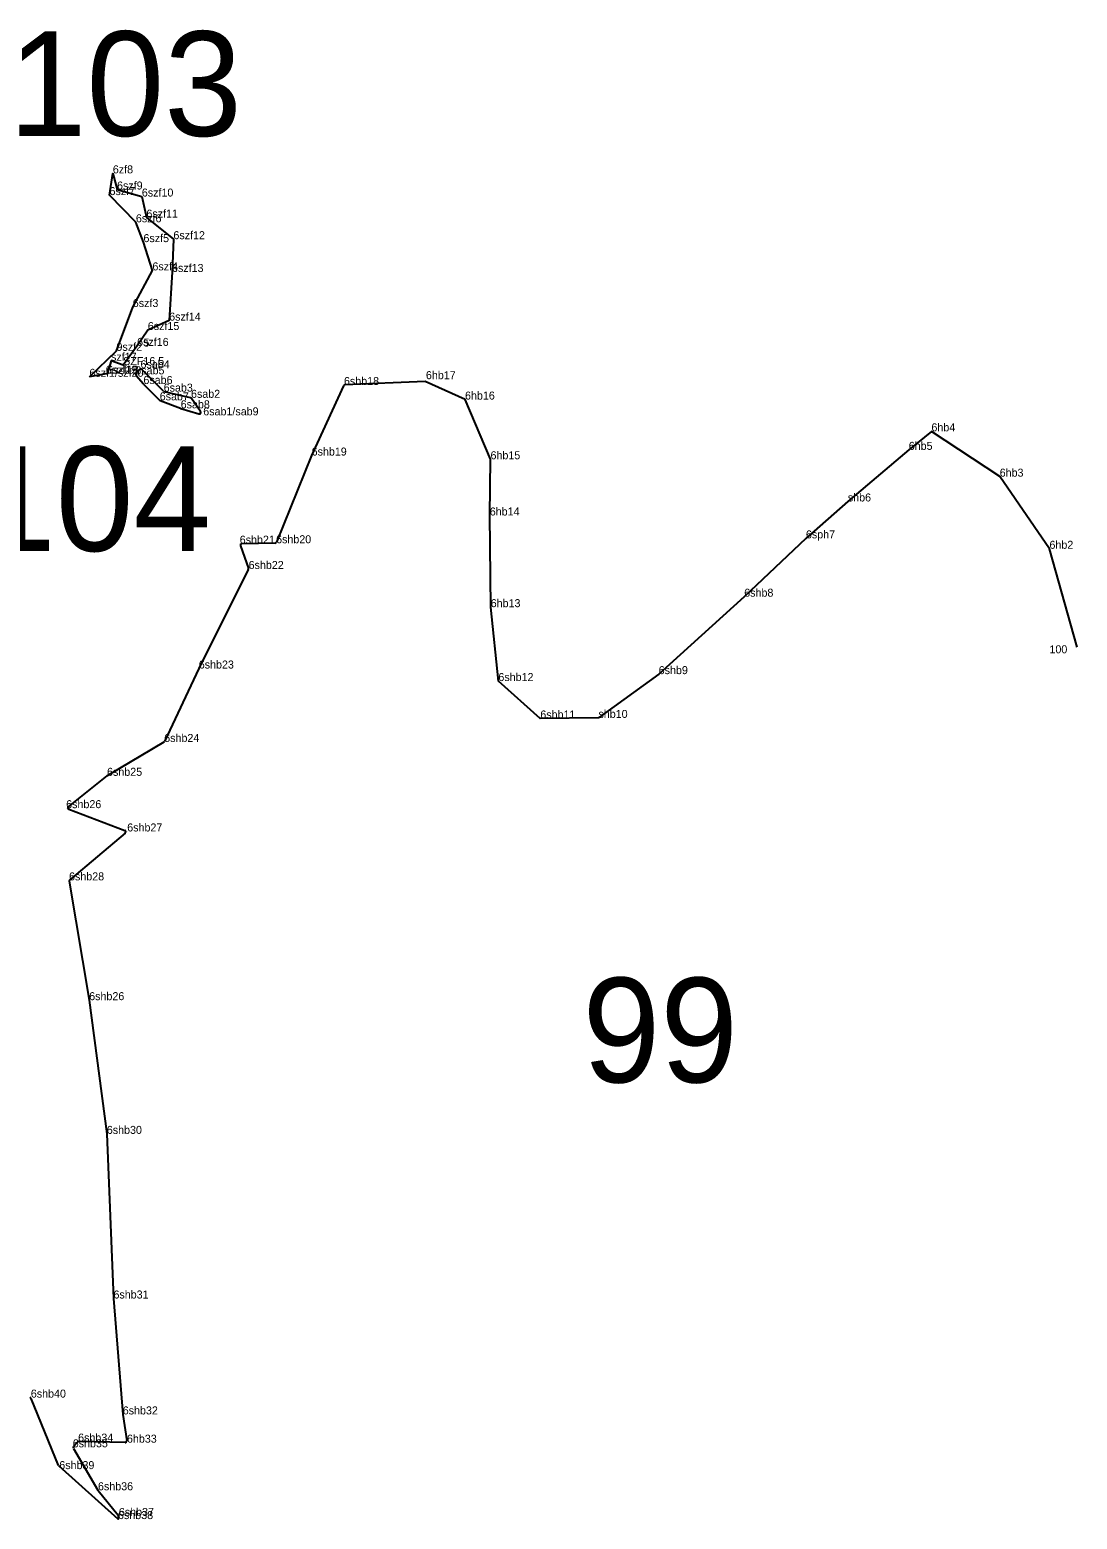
# Model space of a CAD drawing. Extents: x 2072529 to 2268796, y 436423 to 470397.
# Drawn here: x 2138755 to 2139410, y 443063 to 443993 of the extents above; entities that cross this region are included whole.
import ezdxf

# ---------------------------------------------------------------- set-up
doc = ezdxf.new("R2010")
doc.units = 0
for name, color, linetype in [('Default', 7, 'Continuous'), ('Exist Environmental Wetland Boundary Cogo Point CELL', 7, 'Continuous'), ('Exist Hydro Jurisdictional Stream or Body of Water NEU Mitigable', 7, 'Continuous'), ('Exist Hydro Jurisdictional Stream or Body of Water NEU Mitigable Cogo Comment', 7, 'Continuous')]:
    doc.layers.add(name, color=color, linetype=linetype)

msp = doc.modelspace()

# ---------------------------------------------------------------- linework, layer by layer
at = {"layer": 'Exist Environmental Wetland Boundary Cogo Point CELL'}
for p, q in [((2138807.29, 443903.7), (2138807.29, 443903.7)), ((2138809.92, 443893.61), (2138809.92, 443893.61)), ((2138805.21, 443890.14), (2138805.21, 443890.14)), ((2138825.43, 443889.22), (2138825.43, 443889.22)), ((2138821.71, 443873.14), (2138821.71, 443873.14)), ((2138828.27, 443876.07), (2138828.27, 443876.07)), ((2138826.43, 443860.76), (2138826.43, 443860.76)), ((2138845.15, 443862.59), (2138845.15, 443862.59)), ((2138832.03, 443843.09), (2138832.03, 443843.09)), ((2138844.27, 443842.12), (2138844.27, 443842.12)), ((2138819.76, 443820.2), (2138819.76, 443820.2)), ((2138842.51, 443811.72), (2138842.51, 443811.72)), ((2138829.15, 443805.85), (2138829.15, 443805.85)), ((2138809.58, 443792.84), (2138809.58, 443792.84)), ((2138822.46, 443795.91), (2138822.46, 443795.91)), ((2138806.17, 443786.61), (2138806.17, 443786.61)), ((2138813.77, 443783.94), (2138813.77, 443783.94)), ((2138824.6, 443781.95), (2138824.6, 443781.95)), ((2138792.64, 443776.63), (2138792.64, 443776.63)), ((2138802.85, 443778.53), (2138802.85, 443778.53)), ((2138821.33, 443778.15), (2138821.33, 443778.15)), ((2138826.4, 443772.12), (2138826.4, 443772.12)), ((2138951.75, 443771.47), (2138951.75, 443771.47)), ((2139002.26, 443774.07), (2139002.26, 443774.07)), ((2138836.6, 443761.91), (2138836.6, 443761.91)), ((2138839.07, 443767.35), (2138839.07, 443767.35)), ((2138856.15, 443763.48), (2138856.15, 443763.48)), ((2139027.4, 443762.38), (2139027.4, 443762.38)), ((2138849.7, 443756.92), (2138849.7, 443756.92)), ((2138863.8, 443752.52), (2138863.8, 443752.52)), ((2139318.9, 443742.54), (2139318.9, 443742.54)), ((2138931.54, 443727.42), (2138931.54, 443727.42)), ((2139043.35, 443725.09), (2139043.35, 443725.09)), ((2139304.73, 443730.96), (2139304.73, 443730.96)), ((2139361.56, 443714.23), (2139361.56, 443714.23)), ((2139266.65, 443698.73), (2139266.65, 443698.73)), ((2139042.87, 443689.96), (2139042.87, 443689.96)), ((2138886.59, 443672.34), (2138886.59, 443672.34)), ((2138909.33, 443672.62), (2138909.33, 443672.62)), ((2139240.45, 443675.67), (2139240.45, 443675.67)), ((2139392.66, 443669.16), (2139392.66, 443669.16)), ((2138892.16, 443656.55), (2138892.16, 443656.55)), ((2139043.45, 443632.68), (2139043.45, 443632.68)), ((2139201.89, 443639.24), (2139201.89, 443639.24)), ((2139409.05, 443607.29), (2139409.05, 443607.29)), ((2138861.01, 443594.35), (2138861.01, 443594.35)), ((2139048.25, 443586.52), (2139048.25, 443586.52)), ((2139148.45, 443590.85), (2139148.45, 443590.85)), ((2139074.46, 443563.13), (2139074.46, 443563.13)), ((2139110.8, 443563.49), (2139110.8, 443563.49)), ((2138839.4, 443548.48), (2138839.4, 443548.48)), ((2138803.67, 443527.32), (2138803.67, 443527.32)), ((2138778.13, 443507.11), (2138778.13, 443507.11)), ((2138816.28, 443492.56), (2138816.28, 443492.56)), ((2138779.92, 443461.99), (2138779.92, 443461.99)), ((2138792.51, 443387.15), (2138792.51, 443387.15)), ((2138803.54, 443303.6), (2138803.54, 443303.6)), ((2138807.69, 443200.76), (2138807.69, 443200.76)), ((2138756.04, 443138.84), (2138756.04, 443138.84)), ((2138813.49, 443128.34), (2138813.49, 443128.34)), ((2138785.59, 443111.35), (2138785.59, 443111.35)), ((2138816.12, 443110.69), (2138816.12, 443110.69)), ((2138782.24, 443107.8), (2138782.24, 443107.8)), ((2138773.5, 443096.16), (2138773.5, 443096.16)), ((2138773.82, 443094.17), (2138773.82, 443094.17)), ((2138773.82, 443094.17), (2138773.82, 443094.17)), ((2138797.77, 443080.29), (2138797.77, 443080.29)), ((2138797.77, 443080.29), (2138797.77, 443080.29)), ((2138798.01, 443080.95), (2138798.01, 443080.95)), ((2138810.52, 443062.94), (2138810.52, 443062.94)), ((2138811.05, 443064.91), (2138811.05, 443064.91))]:
    msp.add_line(p, q, dxfattribs=at)
at = {"layer": 'Exist Hydro Jurisdictional Stream or Body of Water NEU Mitigable'}
for p, q in [((2138823.9, 443781.13), (2138821.88, 443778.79)), ((2138838.86, 443767.56), (2138825.36, 443781.18)), ((2138821.88, 443777.5), (2138826.37, 443772.16)), ((2138826.42, 443772.1), (2138836.45, 443762.06)), ((2138951.49, 443770.92), (2138931.55, 443727.44)), ((2138951.49, 443770.92), (2138931.55, 443727.44)), ((2138951.49, 443770.92), (2138931.55, 443727.44)), ((2139002.53, 443773.73), (2138952.36, 443771.5)), ((2139002.53, 443773.73), (2138952.36, 443771.5)), ((2139002.53, 443773.73), (2138952.36, 443771.5)), ((2138836.8, 443761.83), (2138849.67, 443756.93)), ((2138855.77, 443763.57), (2138839.35, 443767.29)), ((2138862.12, 443754.92), (2138856.37, 443763.16)), ((2138849.73, 443756.91), (2138861, 443753.39)), ((2138931.53, 443727.4), (2138909.58, 443673.23)), ((2138931.53, 443727.4), (2138909.58, 443673.23)), ((2138931.53, 443727.4), (2138909.58, 443673.23)), ((2138887.06, 443671.03), (2138892.02, 443656.95)), ((2138887.06, 443671.03), (2138892.02, 443656.95)), ((2138887.06, 443671.03), (2138892.02, 443656.95)), ((2138908.66, 443672.61), (2138887.99, 443672.36)), ((2138908.66, 443672.61), (2138887.99, 443672.36)), ((2138908.66, 443672.61), (2138887.99, 443672.36)), ((2138891.97, 443656.17), (2138861.02, 443594.36)), ((2138891.97, 443656.17), (2138861.02, 443594.36)), ((2138891.97, 443656.17), (2138861.02, 443594.36)), ((2138861.01, 443594.34), (2138839.53, 443548.76)), ((2138861.01, 443594.34), (2138839.53, 443548.76)), ((2138861.01, 443594.34), (2138839.53, 443548.76)), ((2138839.13, 443548.33), (2138803.72, 443527.35)), ((2138839.13, 443548.33), (2138803.72, 443527.35)), ((2138839.13, 443548.33), (2138803.72, 443527.35)), ((2138803.61, 443527.28), (2138779.51, 443508.2)), ((2138803.61, 443527.28), (2138779.51, 443508.2)), ((2138803.61, 443527.28), (2138779.51, 443508.2)), ((2138779.77, 443506.48), (2138814.69, 443493.17)), ((2138779.77, 443506.48), (2138814.69, 443493.17)), ((2138779.77, 443506.48), (2138814.69, 443493.17)), ((2138814.98, 443491.47), (2138780.36, 443462.36)), ((2138814.98, 443491.47), (2138780.36, 443462.36)), ((2138814.98, 443491.47), (2138780.36, 443462.36)), ((2138780.02, 443461.43), (2138792.51, 443387.17)), ((2138780.02, 443461.43), (2138792.51, 443387.17)), ((2138780.02, 443461.43), (2138792.51, 443387.17)), ((2138792.51, 443387.13), (2138803.53, 443303.65)), ((2138792.51, 443387.13), (2138803.53, 443303.65)), ((2138792.51, 443387.13), (2138803.53, 443303.65)), ((2138803.54, 443303.56), (2138807.69, 443200.78)), ((2138803.54, 443303.56), (2138807.69, 443200.78)), ((2138803.54, 443303.56), (2138807.69, 443200.78)), ((2138807.69, 443200.74), (2138813.49, 443128.38)), ((2138807.69, 443200.74), (2138813.49, 443128.38)), ((2138807.69, 443200.74), (2138813.49, 443128.38)), ((2138773.41, 443096.38), (2138756.29, 443138.22)), ((2138773.41, 443096.38), (2138756.29, 443138.22)), ((2138773.41, 443096.38), (2138756.29, 443138.22)), ((2138813.5, 443128.31), (2138815.95, 443111.86)), ((2138813.5, 443128.31), (2138815.95, 443111.86)), ((2138813.5, 443128.31), (2138815.95, 443111.86)), ((2138785.29, 443111.03), (2138782.75, 443108.34)), ((2138785.29, 443111.03), (2138782.75, 443108.34)), ((2138785.29, 443111.03), (2138782.75, 443108.34)), ((2138814.94, 443110.72), (2138786.04, 443111.34)), ((2138814.94, 443110.72), (2138786.04, 443111.34)), ((2138814.94, 443110.72), (2138786.04, 443111.34)), ((2138782.62, 443107.15), (2138797.97, 443081.02)), ((2138782.62, 443107.15), (2138797.97, 443081.02)), ((2138782.62, 443107.15), (2138797.97, 443081.02)), ((2138798.06, 443080.89), (2138810.72, 443065.3)), ((2138798.06, 443080.89), (2138810.72, 443065.3)), ((2138798.06, 443080.89), (2138810.72, 443065.3))]:
    msp.add_line(p, q, dxfattribs=at)
for points in [[(2138792.64, 443776.63), (2138809.58, 443792.84), (2138819.76, 443820.2), (2138832.03, 443843.09), (2138826.43, 443860.76), (2138821.71, 443873.14), (2138805.21, 443890.14), (2138807.29, 443903.7), (2138809.92, 443893.61), (2138825.43, 443889.22), (2138828.27, 443876.07), (2138845.15, 443862.59), (2138844.27, 443842.12), (2138842.51, 443811.72), (2138829.15, 443805.85), (2138822.46, 443795.91), (2138813.77, 443783.94), (2138806.17, 443786.61), (2138803.71, 443778.55)], [(2138803.71, 443778.55), (2138802.85, 443778.53), (2138792.64, 443776.63)], [(2139410.01, 443607.77), (2139392.66, 443669.16), (2139361.56, 443714.23), (2139318.9, 443742.54), (2139304.73, 443730.96), (2139266.65, 443698.73), (2139240.45, 443675.67), (2139201.89, 443639.24), (2139148.45, 443590.85), (2139110.8, 443563.49), (2139074.46, 443563.13), (2139048.25, 443586.52), (2139043.45, 443632.68), (2139042.87, 443689.96), (2139043.35, 443725.09), (2139027.4, 443762.38), (2139002.53, 443773.73)], [(2138810.91, 443064.41), (2138810.52, 443062.94), (2138773.67, 443096.01)], [(2138810.91, 443064.41), (2138810.52, 443062.94), (2138773.67, 443096.01)], [(2138810.91, 443064.41), (2138810.52, 443062.94), (2138773.67, 443096.01)]]:
    msp.add_lwpolyline(points, dxfattribs=at)
for centre, start, end in [((2138824.65, 443780.48), 44.73784, 139.25876), ((2138822.64, 443778.14), 139.25876, 220.07395), ((2138827.13, 443772.8), 220.07395, 224.97476), ((2138952.4, 443770.5), 92.54728, 155.3553), ((2138952.4, 443770.5), 92.54728, 155.3553), ((2138952.4, 443770.5), 92.54728, 155.3553), ((2138837.16, 443762.77), 224.97476, 249.151), ((2138839.57, 443768.26), 224.73784, 257.22416), ((2138855.55, 443762.59), 34.93161, 77.22416), ((2138850.02, 443757.87), 249.151, 252.67768), ((2138861.3, 443754.35), 252.67768, 34.93161), ((2138932.46, 443727.02), 155.3553, 157.93516), ((2138932.46, 443727.02), 155.3553, 157.93516), ((2138932.46, 443727.02), 155.3553, 157.93516), ((2138888, 443671.36), 90.69304, 199.42409), ((2138888, 443671.36), 90.69304, 199.42409), ((2138888, 443671.36), 90.69304, 199.42409), ((2138908.65, 443673.61), 270.69304, 337.93516), ((2138908.65, 443673.61), 270.69304, 337.93516), ((2138908.65, 443673.61), 270.69304, 337.93516), ((2138891.07, 443656.62), 333.40106, 19.42409), ((2138891.07, 443656.62), 333.40106, 19.42409), ((2138891.07, 443656.62), 333.40106, 19.42409), ((2138861.91, 443593.91), 153.40106, 154.7682), ((2138861.91, 443593.91), 153.40106, 154.7682), ((2138861.91, 443593.91), 153.40106, 154.7682), ((2138838.62, 443549.19), 300.63818, 334.7682), ((2138838.62, 443549.19), 300.63818, 334.7682), ((2138838.62, 443549.19), 300.63818, 334.7682), ((2138804.23, 443526.49), 120.63818, 128.35754), ((2138804.23, 443526.49), 120.63818, 128.35754), ((2138804.23, 443526.49), 120.63818, 128.35754), ((2138780.13, 443507.42), 128.35754, 249.12519), ((2138780.13, 443507.42), 128.35754, 249.12519), ((2138780.13, 443507.42), 128.35754, 249.12519), ((2138814.34, 443492.23), 310.05468, 69.12519), ((2138814.34, 443492.23), 310.05468, 69.12519), ((2138814.34, 443492.23), 310.05468, 69.12519), ((2138781, 443461.6), 130.05468, 189.54647), ((2138781, 443461.6), 130.05468, 189.54647), ((2138781, 443461.6), 130.05468, 189.54647), ((2138791.52, 443387), 7.5197, 9.54647), ((2138791.52, 443387), 7.5197, 9.54647), ((2138791.52, 443387), 7.5197, 9.54647), ((2138802.54, 443303.52), 2.31084, 7.5197), ((2138802.54, 443303.52), 2.31084, 7.5197), ((2138802.54, 443303.52), 2.31084, 7.5197), ((2138808.69, 443200.82), 182.31083, 184.58125), ((2138808.69, 443200.82), 182.31083, 184.58125), ((2138808.69, 443200.82), 182.31083, 184.58125), ((2138755.37, 443137.84), 22.24359, 89.15534), ((2138755.37, 443137.84), 22.24359, 89.15534), ((2138755.37, 443137.84), 22.24359, 89.15534), ((2138814.49, 443128.46), 184.58125, 188.47331), ((2138814.49, 443128.46), 184.58125, 188.47331), ((2138814.49, 443128.46), 184.58125, 188.47331), ((2138786.01, 443110.34), 88.76161, 136.64179), ((2138786.01, 443110.34), 88.76161, 136.64179), ((2138786.01, 443110.34), 88.76161, 136.64179), ((2138814.96, 443111.71), 268.76161, 8.47331), ((2138814.96, 443111.71), 268.76161, 8.47331), ((2138814.96, 443111.71), 268.76161, 8.47331), ((2138783.48, 443107.66), 136.64179, 210.43541), ((2138783.48, 443107.66), 136.64179, 210.43541), ((2138783.48, 443107.66), 136.64179, 210.43541), ((2138774.33, 443096.75), 202.24359, 228.09634), ((2138774.33, 443096.75), 202.24359, 228.09634), ((2138774.33, 443096.75), 202.24359, 228.09634), ((2138798.83, 443081.52), 210.43541, 219.09735), ((2138798.83, 443081.52), 210.43541, 219.09735), ((2138798.83, 443081.52), 210.43541, 219.09735), ((2138809.95, 443064.67), 345.03597, 39.09735), ((2138809.95, 443064.67), 345.03597, 39.09735), ((2138809.95, 443064.67), 345.03597, 39.09735)]:
    msp.add_arc(centre, 1, start, end, dxfattribs=at)

# ---------------------------------------------------------------- texts
at = {"layer": 'Default'}
for s, p in [('103', (2138742.21, 443927.1)), ('104', (2138722.99, 443667.75)), ('99', (2139100.82, 443335.8))]:
    msp.add_text(s, height=65.34, dxfattribs=at).set_placement(p)
at = {"layer": 'Exist Hydro Jurisdictional Stream or Body of Water NEU Mitigable Cogo Comment'}
for s, p in [('6zf8', (2138807.29, 443903.7)), ('6szf7', (2138805.21, 443890.14)), ('6szf9', (2138809.92, 443893.61)), ('6szf10', (2138825.43, 443889.22)), ('6szf6', (2138821.71, 443873.14)), ('6szf11', (2138828.27, 443876.07)), ('6szf5', (2138826.43, 443860.76)), ('6szf12', (2138845.15, 443862.59)), ('6szf4', (2138832.03, 443843.09)), ('6szf13', (2138844.27, 443842.12)), ('6szf3', (2138819.76, 443820.2)), ('6szf14', (2138842.51, 443811.72)), ('6szf15', (2138829.15, 443805.85)), ('9szf2', (2138809.58, 443792.84)), ('6szf16', (2138822.46, 443795.91)), ('5', (2138826.43, 443795.47)), ('szf17', (2138806.17, 443786.61)), ('SZF16.5', (2138813.77, 443783.94)), ('6szf1/szf20', (2138792.64, 443776.63)), ('6szf19', (2138802.85, 443778.53)), ('6szf18', (2138803.71, 443778.55)), ('6sab5', (2138821.33, 443778.15)), ('6sab4', (2138824.6, 443781.95)), ('6hb17', (2139002.96, 443775.13)), ('6sab6', (2138826.4, 443772.12)), ('6sab3', (2138839.07, 443767.35)), ('6shb18', (2138951.75, 443771.47)), ('6sab7', (2138836.6, 443761.91)), ('6sab8', (2138849.7, 443756.92)), ('6sab2', (2138856.15, 443763.48)), ('6hb16', (2139027.4, 443762.38)), ('6sab1/sab9', (2138863.8, 443752.52)), ('6hb4', (2139318.9, 443742.54)), ('6shb19', (2138931.54, 443727.42)), ('6hb5', (2139304.73, 443730.96)), ('6hb15', (2139043.35, 443725.09)), ('6hb3', (2139361.56, 443714.23)), ('shb6', (2139266.65, 443698.73)), ('6hb14', (2139042.87, 443689.96)), ('6shb21', (2138886.59, 443672.34)), ('6shb20', (2138909.33, 443672.62)), ('6sph7', (2139240.45, 443675.67)), ('6hb2', (2139392.66, 443669.16)), ('6shb22', (2138892.16, 443656.55)), ('6shb8', (2139201.89, 443639.24)), ('6hb13', (2139043.45, 443632.68)), ('100', (2139392.66, 443603.87)), ('6shb23', (2138861.01, 443594.35)), ('6shb9', (2139148.45, 443590.85)), ('6shb12', (2139048.25, 443586.52)), ('6shb11', (2139074.46, 443563.13)), ('shb10', (2139110.8, 443563.49)), ('6shb24', (2138839.4, 443548.48)), ('6shb25', (2138803.67, 443527.32)), ('6shb26', (2138778.13, 443507.11)), ('6shb27', (2138816.28, 443492.56)), ('6shb28', (2138779.92, 443461.99)), ('6shb26', (2138792.51, 443387.15)), ('6shb30', (2138803.54, 443303.6)), ('6shb31', (2138807.69, 443200.76)), ('6shb40', (2138756.04, 443138.84)), ('6shb32', (2138813.49, 443128.34)), ('6shb35', (2138782.24, 443107.8)), ('6shb34', (2138785.59, 443111.35)), ('6hb33', (2138816.12, 443110.69)), ('6shb39', (2138773.82, 443094.17)), ('6shb36', (2138798.01, 443080.95)), ('6shb38', (2138810.52, 443062.94)), ('6shb37', (2138811.05, 443064.91))]:
    msp.add_text(s, height=5, dxfattribs=at).set_placement(p)

doc.saveas('drawing.dxf')
